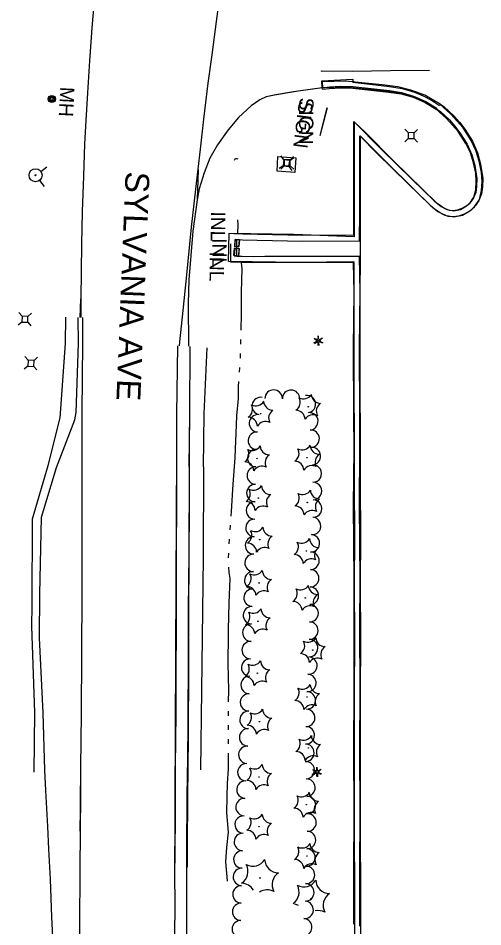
# Model space of a CAD drawing. Extents: x 588843 to 2552415, y 180129 to 269402.
# Drawn here: x 593174.4 to 593368.8, y 184799.9 to 185179.7 of the extents above; entities that cross this region are included whole.
import ezdxf

# ---------------------------------------------------------------- set-up
doc = ezdxf.new("R2010")
doc.units = 0
for name, color, linetype in [('Default', 7, 'Continuous'), ('E_AREA', 7, 'Continuous'), ('E_DRN', 7, 'Continuous'), ('E_DRN_ConcDitch', 7, 'Continuous'), ('E_DRN_Text', 7, 'Continuous'), ('E_DWY', 7, 'Continuous'), ('E_LAND_TreeLine_P', 7, 'Continuous'), ('E_LAND_Vegetation', 7, 'Continuous'), ('E_LTG', 7, 'Continuous'), ('E_RDWY', 7, 'Continuous'), ('E_RDWY_AsphConc', 7, 'Continuous'), ('E_RDWY_C_and_G', 7, 'Continuous'), ('E_RDWY_Gravel', 7, 'Continuous'), ('E_RDWY_PavtEdge', 7, 'Continuous'), ('E_RDWY_Text', 7, 'Continuous'), ('E_SGN', 7, 'Continuous'), ('E_SGN_Text', 7, 'Continuous'), ('E_UTL_AG_Bold', 7, 'Continuous'), ('E_UTL_MH', 7, 'Continuous'), ('E_UTL_MH_Text', 7, 'Continuous'), ('E_UTL_WHydrant', 7, 'Continuous'), ('E_WTR_P', 7, 'Continuous')]:
    doc.layers.add(name, color=color, linetype=linetype)

# ---------------------------------------------------------------- blocks, each defined once
blk = doc.blocks.new('HYD')
at = {"layer": 'Default'}
for p, q in [((-3.84, 3.84), (-8.32, 8.32)), ((3.84, 3.84), (8.32, 8.32))]:
    blk.add_line(p, q, dxfattribs=at)
for radius in [5.48, 0.42]:
    blk.add_circle((0, 0), radius, dxfattribs=at)
blk = doc.blocks.new('MHO')
at = {"layer": 'Default'}
for centre, radius in [((0.08, -0.12), 3), ((0.08, -0.12), 2.43), ((0.07, -0.15), 1.94), ((0.02, -0.16), 1.21)]:
    blk.add_circle(centre, radius, dxfattribs=at)
blk = doc.blocks.new('MHT')
at = {"layer": 'E_UTL_MH_Text'}
blk.add_text('MH', height=12, dxfattribs=at).set_placement((-9.81, -6))
blk = doc.blocks.new('PED')
at = {"layer": 'Default'}
for p, q in [((-2.5, 2.5), (-5.33, 5.33)), ((2.5, 2.5), (5.33, 5.33)), ((-2.5, -2.5), (-5.33, -5.33)), ((2.5, -2.5), (5.33, -5.33))]:
    blk.add_line(p, q, dxfattribs=at)
blk.add_lwpolyline([(-2.5, -2.5), (2.5, -2.5), (2.5, 2.5), (-2.5, 2.5)], close=True, dxfattribs=at)
blk = doc.blocks.new('CULV2')
at = {"layer": 'E_DRN'}
blk.add_arc((19.7, 14.8), 24.6, 216.8699, 323.1301, dxfattribs=at)
blk = doc.blocks.new('INLT_20')
at = {"layer": 'E_DRN_Text'}
blk.add_text('INL', height=12, dxfattribs=at).set_placement((-11.03, -6))
blk = doc.blocks.new('SIGN')
at = {"layer": 'Default'}
blk.add_text('SIGN', height=12, dxfattribs=at).set_placement((-18.55, -6))
blk = doc.blocks.new('LPOL')
at = {"layer": 'Default'}
for p, q in [((-4, 0), (-1.5, 0)), ((-0.75, 1.3), (-2, 3.46)), ((0.75, 1.3), (2, 3.46)), ((1.5, 0), (4, 0)), ((-2, -3.46), (-0.75, -1.3)), ((2, -3.46), (0.75, -1.3))]:
    blk.add_line(p, q, dxfattribs=at)
for radius in [1.5, 1.5, 1.5, 0.125]:
    blk.add_circle((0, 0), radius, dxfattribs=at)
blk = doc.blocks.new('INLT_47_1')
at = {"layer": 'E_DRN_Text'}
blk.add_text('INL', height=39.37, dxfattribs=at).set_placement((-36.2, -19.7))
blk = doc.blocks.new('PED_3')
at = {"layer": 'E_UTL_AG_Bold'}
for p, q in [((-8.2, 8.2), (-17.5, 17.5)), ((8.2, 8.2), (17.5, 17.5)), ((-8.2, -8.2), (-17.5, -17.5)), ((8.2, -8.2), (17.5, -17.5))]:
    blk.add_line(p, q, dxfattribs=at)
blk.add_lwpolyline([(-8.2, -8.2), (8.2, -8.2), (8.2, 8.2), (-8.2, 8.2)], close=True, dxfattribs=at)
blk = doc.blocks.new('LPOL_4')
at = {"layer": 'E_LTG'}
for p, q in [((-13.1, 0), (-4.9, 0)), ((-2.5, 4.3), (-6.6, 11.4)), ((2.5, 4.3), (6.6, 11.4)), ((4.9, 0), (13.1, 0)), ((-6.6, -11.4), (-2.5, -4.3)), ((6.6, -11.4), (2.5, -4.3))]:
    blk.add_line(p, q, dxfattribs=at)
for radius in [4.92, 4.92, 4.92, 0.41]:
    blk.add_circle((0, 0), radius, dxfattribs=at)
blk = doc.blocks.new('SIGN_3')
at = {"layer": 'E_SGN'}
blk.add_text('SIGN', height=39.37, dxfattribs=at).set_placement((-56.1, -19.7))
blk = doc.blocks.new('CTRE_4')
at = {"layer": 'E_LAND_Vegetation'}
blk.add_circle((0, 0), 0.733, dxfattribs=at)
for centre, start, end in [((-39.3, 29.4), 280.2067, 5.9716), ((5.9, 49), 220.2113, 305.9762), ((45.4, 19.3), 160.2113, 245.9762), ((-45.4, -19.3), 340.2113, 65.9762), ((-5.9, -49), 40.2113, 125.9762), ((39.5, -29.6), 100.2511, 185.9272)]:
    blk.add_arc(centre, 25.8, start, end, dxfattribs=at)

msp = doc.modelspace()

# ---------------------------------------------------------------- linework, layer by layer
at = {"layer": 'E_AREA'}
msp.add_lwpolyline([(593290.58, 185121.4), (593290.2, 185115.24), (593282.69, 185115.71), (593283.07, 185121.86)], close=True, dxfattribs=at)
at = {"layer": 'E_DRN'}
for points in [[(593265.17, 185087.18), (593264.94, 185084.24), (593266.76, 185084.1), (593266.99, 185087.04)], [(593265, 185084.35), (593265.16, 185087.21), (593266.94, 185087.11), (593266.78, 185084.25), (593265, 185084.35)], [(593264.6, 185080.45), (593264.85, 185083.53), (593266.83, 185083.37), (593266.58, 185080.29), (593264.6, 185080.45)], [(593265, 185083.38), (593264.8, 185080.34), (593266.68, 185080.21), (593266.88, 185083.26)]]:
    msp.add_lwpolyline(points, close=True, dxfattribs=at)
at = {"layer": 'E_DRN_ConcDitch'}
msp.add_lwpolyline([(593314.86, 185077.85), (593292.01, 185077.65), (593262.39, 185078), (593262.68, 185089.79), (593289.76, 185089.43), (593314.97, 185088.39)], dxfattribs=at)
at = {"layer": 'E_DWY'}
for points in [[(593301.55, 185150.61), (593291.52, 185149.16), (593281.68, 185147.55), (593278.15, 185146.83), (593275.54, 185145.56), (593271.9, 185143.08), (593266.58, 185138.17), (593262.26, 185133.1), (593257.75, 185126.73), (593254.54, 185121.17), (593252.21, 185115.1), (593250.18, 185108.43), (593249.25, 185103.8)], [(593264.63, 185089.76), (593268.4, 185089.54), (593274.47, 185089.48), (593293.55, 185089.01), (593314.77, 185089.09), (593314.79, 185098.7), (593314.81, 185125.39), (593314.87, 185136.53), (593326.41, 185124.86), (593339.11, 185112.43), (593348.42, 185103.43), (593351.31, 185100.99), (593353.72, 185099.77), (593356.67, 185099.24), (593359.43, 185099.77), (593361.93, 185101.3), (593363.52, 185102.55), (593365.04, 185104.87), (593365.84, 185107.99), (593366.01, 185111.42), (593365.82, 185114.92), (593364.88, 185119.27), (593363.59, 185123.43), (593361.71, 185127.33), (593358.53, 185132.34), (593353.65, 185137.85), (593349.16, 185141.86), (593343.48, 185145.21), (593337.98, 185147.21), (593332.84, 185148.56), (593326.48, 185149.34), (593315.12, 185150.51), (593311.4, 185150.85), (593301.71, 185150.6)], [(593317.4, 184800.08), (593317.35, 184822.65), (593317.48, 184848.18), (593317.36, 184873.65), (593317.46, 184898.63), (593317.41, 184925.38), (593317.42, 184944.77), (593317.22, 184976.09), (593317.41, 184999.37), (593317.37, 185013.92), (593317.25, 185041.97), (593317.47, 185065.22), (593317.19, 185080.02), (593287.38, 185080.08), (593277.55, 185080.02), (593273.02, 185079.9), (593268.04, 185080.02), (593265.88, 185080.14), (593265.94, 185087.18), (593268.32, 185087.04), (593274.43, 185086.98), (593293.53, 185086.51), (593317.27, 185086.6), (593317.29, 185098.7), (593317.31, 185125.38), (593317.34, 185130.48), (593324.65, 185123.09), (593337.37, 185110.64), (593346.74, 185101.58), (593349.92, 185098.89), (593352.92, 185097.38), (593356.68, 185096.69), (593360.34, 185097.4), (593363.36, 185099.24), (593365.39, 185100.84), (593367.36, 185103.85), (593368.32, 185107.62), (593368.51, 185111.43), (593368.31, 185115.25), (593367.3, 185119.91), (593365.92, 185124.35), (593363.9, 185128.55), (593360.53, 185133.85), (593355.42, 185139.62), (593350.64, 185143.89), (593344.55, 185147.49), (593338.73, 185149.6), (593333.31, 185151.02), (593326.76, 185151.83), (593315.36, 185153), (593311.48, 185153.36), (593301.65, 185153.1)], [(593301.65, 185153.1), (593301.71, 185150.6), (593295.6, 185149.73), (593289.55, 185148.9), (593282.15, 185147.73), (593280.09, 185147.26)], [(593350.48, 185144.13), (593352.62, 185142.6), (593356.62, 185138.92), (593359.08, 185136.22), (593361.26, 185133.26), (593364.46, 185128.28), (593366.57, 185123.48), (593367.87, 185118.64), (593368.82, 185112.78), (593368.62, 185109.17), (593368.32, 185106.22), (593367.1, 185103.48), (593365.76, 185101.43), (593363.76, 185099.36), (593361.06, 185097.85), (593358.61, 185096.98), (593356.3, 185096.72), (593354.29, 185096.83), (593352.05, 185097.78), (593350.58, 185098.58), (593348.08, 185100.31), (593329.69, 185118.35), (593317.97, 185130.12), (593317.52, 185130.55), (593317.43, 185106.38), (593317.47, 185088.35)], [(593349.49, 185141.77), (593351.04, 185140.66), (593354.85, 185137.16), (593357.15, 185134.63), (593359.2, 185131.84), (593362.25, 185127.09), (593364.21, 185122.65), (593365.42, 185118.12), (593366.31, 185112.64), (593366.12, 185109.37), (593365.88, 185106.87), (593364.9, 185104.68), (593363.79, 185103), (593362.22, 185101.37), (593360.02, 185100.14), (593358.04, 185099.44), (593356.23, 185099.23), (593354.86, 185099.3), (593353.14, 185100.04), (593351.89, 185100.71), (593349.68, 185102.24), (593331.45, 185120.12), (593319.72, 185131.91), (593315.04, 185136.39), (593314.93, 185106.38), (593314.97, 185088.35)], [(593314.9, 184800.97), (593314.85, 184822.66), (593314.98, 184848.18), (593314.86, 184873.65), (593314.96, 184898.63), (593314.91, 184925.38), (593314.92, 184944.76), (593314.72, 184976.1), (593314.91, 184999.37), (593314.87, 185013.91), (593314.75, 185041.98), (593314.97, 185065.21), (593314.74, 185077.53), (593287.39, 185077.58), (593277.59, 185077.52), (593273.02, 185077.4), (593267.94, 185077.52), (593263.36, 185077.78), (593263.43, 185085.39)], [(593317.47, 185088.35), (593317.28, 185056.14), (593317.37, 185025.11), (593317.42, 185004.37), (593317.51, 184983.79), (593317.57, 184964.08), (593317.52, 184942), (593317.56, 184920.92), (593317.48, 184896.22), (593317.51, 184879.42), (593317.51, 184855.62), (593317.43, 184837.02), (593317.61, 184816.94), (593317.6, 184792.7), (593317.65, 184768.85), (593317.43, 184741.67)], [(593314.86, 185077.85), (593314.78, 185056.14), (593314.87, 185025.1), (593314.92, 185004.36), (593315.01, 184983.78), (593315.07, 184964.08), (593315.02, 184942.01), (593315.06, 184920.92), (593314.98, 184896.22), (593315.01, 184879.42), (593315.01, 184855.63), (593314.93, 184837.02), (593315.11, 184816.93), (593315.1, 184792.7), (593315.15, 184768.86), (593314.93, 184741.69)]]:
    msp.add_lwpolyline(points, dxfattribs=at)
at = {"layer": 'E_LAND_TreeLine_P'}
for centre, start, end in [((593275.86, 185017.57), 79.1213, 259.1213), ((593281.28, 185020.69), 359.2605, 179.2605), ((593288.58, 185020.6), 359.2605, 179.2605), ((593295.21, 185018.4), 280.3463, 100.3463), ((593274.72, 185010.37), 86.4255, 266.4255), ((593296.22, 185011.18), 274.5204, 94.5204), ((593274.26, 185003.09), 86.4255, 266.4255), ((593296.78, 185003.91), 274.0104, 94.0104), ((593273.99, 184995.8), 88.426, 268.426), ((593297.29, 184996.62), 274.0104, 94.0104), ((593273.79, 184988.5), 88.7088, 268.7088), ((593297.7, 184989.34), 270.4283, 90.4283), ((593273.63, 184981.2), 88.7088, 268.7088), ((593297.75, 184982.04), 270.4283, 90.4283), ((593273.44, 184973.91), 88.3835, 268.3835), ((593297.81, 184974.74), 270.4283, 90.4283), ((593273.24, 184966.61), 88.3835, 268.3835), ((593297.37, 184967.46), 266.1905, 86.1905), ((593296.88, 184960.18), 266.1905, 86.1905), ((593273.05, 184959.31), 88.7279, 268.7279), ((593296.7, 184952.88), 269.1048, 89.1048), ((593272.88, 184952.02), 88.7279, 268.7279), ((593296.58, 184945.58), 269.1048, 89.1048), ((593272.72, 184944.72), 88.7279, 268.7279), ((593272.46, 184937.43), 87.9254, 267.9254), ((593296.47, 184938.29), 269.1048, 89.1048), ((593272.2, 184930.13), 87.9254, 267.9254), ((593296.36, 184930.99), 269.1048, 89.1048), ((593271.94, 184922.84), 88.058, 268.058), ((593296.24, 184923.69), 269.1048, 89.1048), ((593271.69, 184915.54), 88.058, 268.058), ((593296.13, 184916.39), 269.1048, 89.1048), ((593271.44, 184908.25), 88.1707, 268.1707), ((593295.82, 184909.1), 266.7958, 86.7958), ((593271.21, 184900.95), 88.1707, 268.1707), ((593295.42, 184901.81), 266.7958, 86.7958), ((593270.98, 184893.66), 88.1707, 268.1707), ((593295.15, 184894.52), 268.2479, 88.2479), ((593270.79, 184886.36), 88.5038, 268.5038), ((593294.92, 184887.22), 268.2479, 88.2479), ((593270.6, 184879.07), 88.5038, 268.5038), ((593294.75, 184879.93), 268.6489, 88.6489), ((593294.57, 184872.63), 268.5887, 88.5887), ((593270.25, 184871.78), 86.9791, 266.9791), ((593294.71, 184865.34), 272.227, 92.227), ((593269.87, 184864.49), 86.9791, 266.9791), ((593294.99, 184858.04), 272.1833, 92.1833), ((593269.48, 184857.2), 86.9791, 266.9791), ((593269.1, 184849.91), 86.9791, 266.9791), ((593295.26, 184850.75), 272.1833, 92.1833), ((593268.71, 184842.62), 86.9791, 266.9791), ((593295.48, 184843.46), 268.2223, 88.2223), ((593268.41, 184835.33), 88.2446, 268.2446), ((593295.25, 184836.16), 268.2223, 88.2223), ((593268.19, 184828.03), 88.2446, 268.2446), ((593295.02, 184828.87), 268.2223, 88.2223), ((593267.97, 184820.74), 88.2446, 268.2446), ((593294.8, 184821.57), 268.1171, 88.1171), ((593267.82, 184813.44), 88.8627, 268.8627), ((593294.56, 184814.28), 268.1171, 88.1171), ((593267.68, 184806.14), 88.8627, 268.8627), ((593294.26, 184806.98), 265.4574, 85.4574), ((593267.54, 184798.85), 89.0211, 269.0211), ((593293.68, 184799.71), 265.4574, 85.4574)]:
    msp.add_arc(centre, 3.65, start, end, dxfattribs=at)
at = {"layer": 'E_LAND_Vegetation'}
for centre in [(593275.59, 184820.25), (593296.95, 184811.6)]:
    msp.add_circle(centre, 0.167, dxfattribs=at)
for centre, radius, start, end in [((593272.54, 184831.1), 5.9, 242.8511, 328.616), ((593283.41, 184828.29), 5.9, 182.8464, 268.6113), ((593264.66, 184823.03), 5.9, 302.8511, 28.616), ((593286.52, 184817.47), 5.9, 122.8511, 208.616), ((593293.89, 184822.46), 5.9, 242.8511, 328.616), ((593304.77, 184819.65), 5.9, 182.8464, 268.6113), ((593267.72, 184812.17), 5.91, 30.9979, 88.5669), ((593286.02, 184814.38), 5.9, 305.354, 28.616), ((593278.65, 184809.4), 5.9, 62.8511, 123.3111), ((593307.87, 184808.83), 5.9, 122.8511, 208.616), ((593289.07, 184803.52), 5.91, 63.3965, 79.4455), ((593300, 184800.75), 5.9, 62.8511, 103.6186)]:
    msp.add_arc(centre, radius, start, end, dxfattribs=at)
at = {"layer": 'E_RDWY'}
for points in [[(593229.75, 185344.39), (593228.74, 185338.48), (593225.9, 185324.71), (593224.11, 185314.81), (593221.31, 185299.66), (593219.1, 185286.27), (593216.35, 185268.31), (593214.44, 185255.05), (593212.81, 185243.32), (593211.42, 185233.23), (593210.18, 185222.75), (593208.56, 185209.67), (593207.25, 185198.27), (593206.31, 185188.73), (593205.22, 185175.67), (593204.19, 185161.83), (593203.37, 185148.48), (593202.75, 185137.01), (593202.17, 185127.15), (593201.68, 185113.66), (593201.21, 185098.92), (593200.87, 185085.43), (593200.59, 185062.46), (593200.61, 185054.59)], [(593241.94, 185042.69), (593242.07, 185044.43), (593243.46, 185057.46), (593244.75, 185070.98), (593246.92, 185092.4), (593248.71, 185108.2), (593250.63, 185125), (593252.09, 185137.47), (593253.87, 185152.57), (593255.5, 185164.44), (593257.32, 185178.27), (593259.58, 185195.12), (593261.85, 185213.17), (593263.77, 185226.77), (593264.92, 185236.57), (593266.67, 185248.98), (593268.41, 185260.06), (593271.46, 185280.49), (593273.1, 185290.92), (593275.78, 185306.6), (593278.62, 185322.02), (593280.53, 185331.47), (593282.48, 185343.12)], [(593240.03, 184826.45), (593240.18, 184850.68), (593240.21, 184881.52), (593240.37, 184913.08), (593240.48, 184943.8), (593240.7, 184970.85), (593240.78, 184998.19), (593240.83, 185003.42)], [(593200.47, 184866.66), (593200.47, 184853.69), (593200.36, 184841.27), (593200.2, 184822.42), (593200.05, 184801.47), (593199.97, 184782.99), (593199.9, 184757.92), (593199.88, 184743.22)], [(593239.88, 184743.09), (593239.88, 184756.35), (593239.95, 184774.33), (593239.83, 184790.03), (593240.01, 184806.78), (593239.95, 184824.58), (593240.05, 184842.91), (593240.04, 184864.07), (593240.06, 184866.97)], [(593200.37, 184839.87), (593200.41, 184848.86), (593200.5, 184858.78)]]:
    msp.add_lwpolyline(points, dxfattribs=at)
at = {"layer": 'E_RDWY_AsphConc'}
for points in [[(593301.17, 185157.61), (593301.52, 185157.65), (593314.3, 185157.61), (593330.16, 185157.84), (593346.51, 185157.92)], [(593185.57, 184865.41), (593184.87, 184889.27), (593183.34, 184920.65), (593183.45, 184938.94), (593184.17, 184971.11), (593190.45, 184991.92), (593198.15, 185011.86), (593198.66, 185014.83), (593199.69, 185043.71), (593199.53, 185054.65)], [(593245.97, 184992.22), (593246.24, 185014.27), (593246.34, 185042.51)], [(593245.97, 184992.22), (593245.75, 184953.82), (593245.24, 184866.45)]]:
    msp.add_lwpolyline(points, dxfattribs=at)
at = {"layer": 'E_RDWY_C_and_G'}
for points in [[(593301.67, 185150.04), (593301.54, 185150.64), (593301.43, 185153.49), (593314.42, 185154.21), (593314.46, 185152.91), (593329.82, 185151.18), (593335.06, 185150.32), (593340.16, 185148.82), (593340.16, 185148.82), (593343.86, 185147.27), (593347.4, 185145.39), (593350.75, 185143.18), (593350.75, 185143.18)], [(593301.54, 185150.64), (593304.6, 185151.05), (593309.2, 185151.23), (593309.2, 185151.23), (593314.35, 185151.09), (593314.35, 185151.09), (593329.7, 185149.43), (593334.84, 185148.63), (593339.83, 185147.17), (593339.83, 185147.17), (593344.96, 185144.89), (593349.71, 185141.9), (593349.71, 185141.9)], [(593301.67, 185150.04), (593304.58, 185150.38), (593309.42, 185150.61), (593309.42, 185150.61), (593314.35, 185150.46), (593314.35, 185150.46), (593329.55, 185148.78), (593334.69, 185148.05), (593339.69, 185146.66), (593339.69, 185146.66), (593344.69, 185144.51), (593349.35, 185141.69), (593349.35, 185141.69)]]:
    msp.add_lwpolyline(points, dxfattribs=at)
at = {"layer": 'E_RDWY_Gravel'}
for points in [[(593249.65, 185116.43), (593249.25, 185103.8), (593247.52, 185090.74), (593245.8, 185070.4), (593245.56, 185060.39), (593245.63, 185042.54)], [(593200.26, 185054.61), (593200.59, 185062.46)], [(593181.11, 184864.53), (593181.3, 184889.41), (593180.11, 184925.51), (593180.28, 184934.15), (593180.41, 184970.45), (593186.93, 184992.76), (593192.01, 185012.65), (593194.15, 185043.66), (593194.26, 185054.67)], [(593251.89, 184992.14), (593252.17, 185014.26), (593253.42, 185041.9)], [(593246.08, 185022.4), (593246.12, 185020.37), (593245.96, 184994.66), (593245.93, 184973.85), (593245.85, 184955.8), (593245.57, 184932.49), (593245.59, 184909.18), (593245.46, 184878.97), (593245.3, 184854), (593245.13, 184833.43), (593245.13, 184824.73)], [(593251.89, 184992.14), (593251.85, 184954.05), (593250.67, 184865.54)], [(593191.41, 184743.72), (593190.71, 184754.99), (593190.07, 184770.91), (593189.25, 184787.31), (593188.54, 184803.83), (593187.89, 184819.83), (593187.25, 184832.36), (593186.82, 184841.82), (593185.93, 184856.85), (593185.53, 184865.4)], [(593245.16, 184866.46), (593244.86, 184835.18), (593244.83, 184794.23), (593244.63, 184743.38)]]:
    msp.add_lwpolyline(points, dxfattribs=at)
at = {"layer": 'E_RDWY_PavtEdge'}
for points in [[(593200.55, 184866.67), (593200.93, 184888.73), (593201.1, 184939.31), (593201.16, 184992.38), (593201.13, 185015.02), (593201.38, 185043.83), (593201.38, 185054.56)], [(593240.27, 184866.96), (593240.52, 184889.02), (593240.58, 184941.46), (593240.79, 184992.13), (593240.79, 185014.21), (593241.23, 185042.72)]]:
    msp.add_lwpolyline(points, dxfattribs=at)
at = {"layer": 'E_SGN'}
msp.add_line((593303.7, 185142.29), (593300.64, 185130.56), dxfattribs=at)
msp.add_lwpolyline([(593300.68, 185130.65), (593303.7, 185142.29)], dxfattribs=at)
at = {"layer": 'E_WTR_P'}
for points in [[(593266.21, 185095.47), (593266.32, 185093.28), (593266.22, 185089.83)], [(593267.76, 185077.4), (593267.98, 185074.87), (593267.75, 185065.22), (593267.64, 185055.99), (593267.5, 185049.23)], [(593267.42, 185045.34), (593267.38, 185043.4)], [(593267.31, 185039.51), (593267.27, 185037.56)], [(593267.04, 185033.68), (593266.91, 185031.75)], [(593266.64, 185027.87), (593266.49, 185025.72), (593266.46, 185020.78), (593265.69, 185013.48), (593265.44, 185006.03), (593265.24, 184999.72)], [(593265.24, 184999.72), (593265.11, 184995.89), (593264.19, 184984.96), (593263.49, 184973.55), (593263.34, 184971.59)], [(593263.04, 184967.71), (593262.9, 184965.77)], [(593262.68, 184961.89), (593262.57, 184959.95)], [(593262.36, 184956.06), (593262.26, 184954.12)], [(593262.35, 184950.24), (593262.49, 184947.94), (593262.98, 184945.44), (593262.47, 184935.2), (593262.25, 184924.21), (593262.24, 184922.11)], [(593262.24, 184922.11), (593262.15, 184909.97), (593262.34, 184898.83), (593262.25, 184893.91)], [(593262.19, 184890.02), (593262.2, 184888.07)], [(593262.23, 184884.19), (593262.24, 184882.24)], [(593262.26, 184878.35), (593262.27, 184877.41), (593262.27, 184876.41)], [(593262.26, 184872.52), (593262.25, 184865.89), (593261.88, 184859.76), (593261.72, 184854.38), (593261.51, 184847.58), (593261.82, 184844.35)], [(593261.82, 184844.34), (593262.29, 184839.47), (593261.51, 184833), (593261.16, 184826.96), (593261.78, 184819.15), (593261.78, 184818.96)]]:
    msp.add_lwpolyline(points, dxfattribs=at)

# ---------------------------------------------------------------- block references
at = {"layer": 'E_DRN', "xscale": 0.047109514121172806, "yscale": 0.047109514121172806, "rotation": -165.18653492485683}
msp.add_blockref('CULV2', (593266.49, 185120.76), dxfattribs=at)
at = {"layer": 'E_DRN_Text'}
for name, p, xscale, yscale, rotation in [('INLT_20', (593258.03, 185093.41), 0.5000000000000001, 0.5, -90.72490345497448), ('INLT_47_1', (593258.59, 185082.21), 0.1524003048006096, 0.1524003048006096, -90.21819803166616), ('INLT_20', (593257.52, 185076.65), 0.5000000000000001, 0.5, -90.72490345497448)]:
    msp.add_blockref(name, p, dxfattribs=dict(at, xscale=xscale, yscale=yscale, rotation=rotation))
at = {"layer": 'E_LAND_Vegetation', "xscale": 0.1524003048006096, "yscale": 0.1524003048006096, "rotation": -97.36026881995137}
for p in [(593295.76, 185017.26), (593275.82, 185014.37), (593295.27, 184995.97), (593274.33, 184995.72), (593274.88, 184979.1), (593295.37, 184977.25), (593275.49, 184961.74), (593295, 184956.96), (593275.2, 184943.65), (593294.51, 184937.38), (593274.68, 184927.61), (593297.64, 184915.54), (593274.47, 184905.89), (593295.3, 184895.92), (593275.36, 184885.63), (593295.79, 184874.62), (593275.2, 184862.52), (593294.93, 184850.91), (593275.2, 184841.71), (593295.21, 184829.49)]:
    msp.add_blockref('CTRE_4', p, dxfattribs=at)
at = {"layer": 'E_LTG'}
for name, p, xscale, yscale, rotation in [('LPOL', (593299.84, 185044.95), 0.5000000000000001, 0.5, -90.72490345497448), ('LPOL_4', (593300.03, 185044.9), 0.1524003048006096, 0.15240030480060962, -84.36014555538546), ('LPOL', (593299.2, 184864.64), 0.5000000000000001, 0.5, -90.72490345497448), ('LPOL_4', (593299.5, 184864.61), 0.1524003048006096, 0.15240030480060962, -84.36014555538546)]:
    msp.add_blockref(name, p, dxfattribs=dict(at, xscale=xscale, yscale=yscale, rotation=rotation))
at = {"layer": 'E_SGN_Text'}
for name, p, xscale, yscale, rotation in [('SIGN', (593294.92, 185137.22), 0.5000000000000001, 0.5, -90.72490345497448), ('SIGN_3', (593293.82, 185136.4), 0.1524003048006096, 0.15240030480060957, -97.28543004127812)]:
    msp.add_blockref(name, p, dxfattribs=dict(at, xscale=xscale, yscale=yscale, rotation=rotation))
at = {"layer": 'E_UTL_AG_Bold'}
for name, p, xscale, yscale, rotation in [('PED', (593338.81, 185130.62), 0.5000000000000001, 0.5, -90.72490345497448), ('PED', (593286.62, 185119.11), 0.5, 0.5, -98.33108331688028), ('PED_3', (593286.96, 185119.25), 0.1524003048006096, 0.1524003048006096, -89.2544447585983), ('PED', (593177.18, 185053.89), 0.5000000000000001, 0.5, -92.95824964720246), ('PED', (593179.74, 185035.46), 0.5000000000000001, 0.5, -92.95824964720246)]:
    msp.add_blockref(name, p, dxfattribs=dict(at, xscale=xscale, yscale=yscale, rotation=rotation))
at = {"layer": 'E_UTL_MH', "xscale": 0.49999999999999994, "yscale": 0.49999999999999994, "rotation": -97.93561972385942}
msp.add_blockref('MHO', (593188.55, 185145.96), dxfattribs=at)
at = {"layer": 'E_UTL_MH_Text', "xscale": 0.5000000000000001, "yscale": 0.5, "rotation": -92.95824964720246}
msp.add_blockref('MHT', (593194.74, 185146.06), dxfattribs=at)
at = {"layer": 'E_UTL_WHydrant', "xscale": 0.49999999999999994, "yscale": 0.49999999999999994, "rotation": -97.93561972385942}
msp.add_blockref('HYD', (593181.69, 185114.04), dxfattribs=at)

# ---------------------------------------------------------------- texts
at = {"layer": 'E_RDWY_Text'}
msp.add_text('SYLVANIA AVE', height=10, rotation=267.6769, dxfattribs=at).set_placement((593219.37, 185115.77))

doc.saveas('drawing.dxf')
